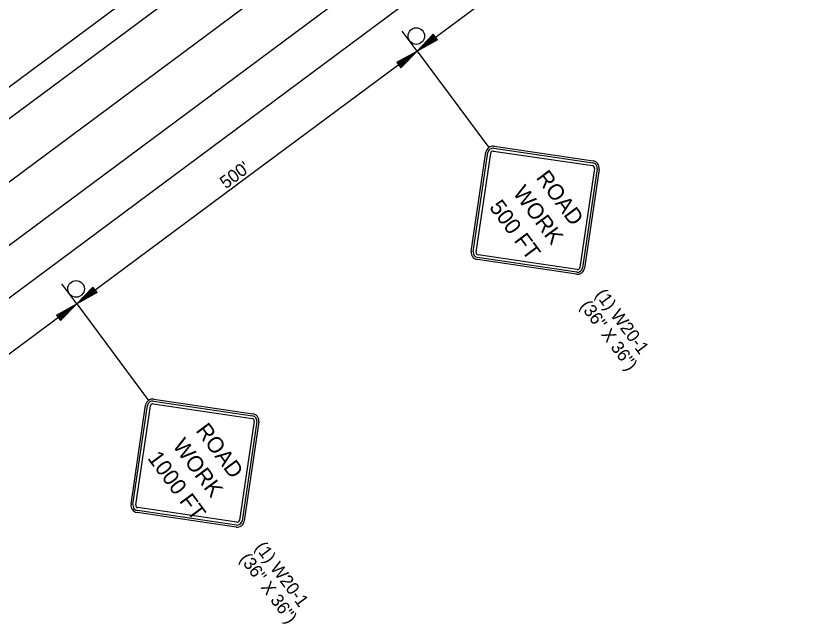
# Model space of a CAD drawing. Extents: x 998982 to 1000630, y 1875366 to 1876934.
# Drawn here: x 999363.5 to 999743.7, y 1875480.6 to 1875767.2 of the extents above; entities that cross this region are included whole.
import ezdxf

# ---------------------------------------------------------------- set-up
doc = ezdxf.new("R2010")
doc.units = 0
for name, color, linetype in [('P_TC_Signs_Temporary', 7, 'Continuous'), ('R_Border Prem', 7, 'Continuous'), ('R_Draft', 7, 'Continuous'), ('STAMP', 7, 'Continuous')]:
    doc.layers.add(name, color=color, linetype=linetype)

msp = doc.modelspace()

# ---------------------------------------------------------------- linework, layer by layer
at = {"layer": 'P_TC_Signs_Temporary'}
for p, q in [((999588.87, 1875704.91), (999635.61, 1875698)), ((999589, 1875705.83), (999635.75, 1875698.93)), ((999578.27, 1875656.25), (999585.17, 1875702.99)), ((999579.19, 1875656.11), (999586.1, 1875702.85)), ((999580.49, 1875655.92), (999587.4, 1875702.66)), ((999588.68, 1875703.61), (999635.42, 1875696.7)), ((999636.37, 1875695.42), (999629.46, 1875648.68)), ((999637.66, 1875695.23), (999630.76, 1875648.49)), ((999638.59, 1875695.1), (999631.69, 1875648.35)), ((999627.85, 1875645.51), (999581.11, 1875652.41)), ((999627.99, 1875646.43), (999581.25, 1875653.34)), ((999628.18, 1875647.73), (999581.44, 1875654.64)), ((999428.43, 1875586.6), (999475.17, 1875579.7)), ((999417.69, 1875537.01), (999424.6, 1875583.76)), ((999418.62, 1875536.88), (999425.53, 1875583.62)), ((999419.92, 1875536.68), (999426.82, 1875583.43)), ((999428.1, 1875584.38), (999474.84, 1875577.47)), ((999428.29, 1875585.67), (999475.04, 1875578.77)), ((999475.79, 1875576.19), (999468.89, 1875529.45)), ((999477.09, 1875576), (999470.19, 1875529.26)), ((999478.02, 1875575.86), (999471.11, 1875529.12)), ((999467.28, 1875526.28), (999420.54, 1875533.18)), ((999467.42, 1875527.2), (999420.68, 1875534.11)), ((999467.61, 1875528.5), (999420.87, 1875535.41))]:
    msp.add_line(p, q, dxfattribs=at)
for centre, radius, start, end in [((999588.51, 1875702.49), 3.38, 81.5953, 171.5953), ((999588.51, 1875702.49), 2.44, 81.5953, 171.5953), ((999588.51, 1875702.49), 1.12, 81.5953, 171.5953), ((999635.25, 1875695.59), 1.13, 351.5953, 81.5953), ((999635.25, 1875695.59), 2.44, 351.5953, 81.5953), ((999635.25, 1875695.59), 3.37, 351.5953, 81.5953), ((999581.6, 1875655.75), 3.37, 171.5953, 261.5953), ((999581.6, 1875655.75), 2.44, 171.5953, 261.5953), ((999581.6, 1875655.75), 1.13, 171.5953, 261.5953), ((999628.35, 1875648.85), 3.38, 261.5953, 351.5953), ((999628.35, 1875648.85), 2.44, 261.5953, 351.5953), ((999628.35, 1875648.85), 1.12, 261.5953, 351.5953), ((999427.94, 1875583.26), 3.38, 81.5953, 171.5953), ((999427.94, 1875583.26), 2.44, 81.5953, 171.5953), ((999427.94, 1875583.26), 1.12, 81.5953, 171.5953), ((999474.68, 1875576.36), 2.44, 351.5953, 81.5953), ((999474.68, 1875576.36), 3.37, 351.5953, 81.5953), ((999474.68, 1875576.36), 1.13, 351.5953, 81.5953), ((999421.03, 1875536.52), 3.37, 171.5953, 261.5953), ((999421.03, 1875536.52), 2.44, 171.5953, 261.5953), ((999421.03, 1875536.52), 1.13, 171.5953, 261.5953), ((999467.77, 1875529.61), 1.12, 261.5953, 351.5953), ((999467.77, 1875529.61), 3.38, 261.5953, 351.5953), ((999467.77, 1875529.61), 2.44, 261.5953, 351.5953)]:
    msp.add_arc(centre, radius, start, end, dxfattribs=at)
at = {"layer": 'R_Draft'}
for p, q in [((999192.61, 1875564.71), (999743.69, 1875973.9)), ((999171.2, 1875593.53), (999643.2, 1875944.01)), ((999178.34, 1875583.93), (999650.33, 1875934.4)), ((999206.88, 1875545.49), (999678.87, 1875895.96)), ((999218.77, 1875529.47), (999690.77, 1875879.94)), ((999713.25, 1875869.99), (999552.67, 1875750.76)), ((999560.31, 1875758.68), (999552.67, 1875750.76)), ((999560.48, 1875758.46), (999554.11, 1875751.87)), ((999560.65, 1875758.24), (999555.6, 1875753)), ((999560.81, 1875758.03), (999557.03, 1875754.11)), ((999560.98, 1875757.81), (999558.5, 1875755.23)), ((999561.15, 1875757.59), (999559.94, 1875756.34)), ((999562.29, 1875756.09), (999560.31, 1875758.68)), ((999562.29, 1875756.09), (999552.67, 1875750.76)), ((999562.13, 1875756.3), (999554.11, 1875751.87)), ((999561.96, 1875756.53), (999555.6, 1875753)), ((999561.79, 1875756.74), (999557.03, 1875754.11)), ((999561.62, 1875756.97), (999558.5, 1875755.23)), ((999561.46, 1875757.18), (999559.94, 1875756.34)), ((999552.67, 1875750.76), (999472.39, 1875691.14)), ((999543.05, 1875745.43), (999552.67, 1875750.76)), ((999545.04, 1875742.84), (999552.67, 1875750.76)), ((999552.67, 1875750.76), (999586.5, 1875705.2)), ((999543.22, 1875745.21), (999551.23, 1875749.65)), ((999543.38, 1875744.99), (999549.75, 1875748.51)), ((999543.55, 1875744.78), (999548.31, 1875747.41)), ((999543.72, 1875744.55), (999546.85, 1875746.29)), ((999544.37, 1875743.71), (999546.85, 1875746.29)), ((999544.54, 1875743.49), (999548.31, 1875747.41)), ((999544.7, 1875743.28), (999549.75, 1875748.51)), ((999544.87, 1875743.05), (999551.23, 1875749.65)), ((999543.05, 1875745.43), (999545.04, 1875742.84)), ((999543.89, 1875744.34), (999545.41, 1875745.18)), ((999544.2, 1875743.93), (999545.41, 1875745.18)), ((999472.39, 1875691.14), (999392.1, 1875631.53)), ((999399.74, 1875639.45), (999392.1, 1875631.53)), ((999401.72, 1875636.86), (999392.1, 1875631.53)), ((999399.9, 1875639.23), (999393.54, 1875632.64)), ((999401.56, 1875637.07), (999393.54, 1875632.64)), ((999400.07, 1875639.01), (999395.02, 1875633.77)), ((999401.39, 1875637.29), (999395.02, 1875633.77)), ((999400.24, 1875638.8), (999396.46, 1875634.88)), ((999401.22, 1875637.51), (999396.46, 1875634.88)), ((999400.41, 1875638.58), (999397.93, 1875636)), ((999401.05, 1875637.73), (999397.93, 1875636)), ((999400.57, 1875638.36), (999399.37, 1875637.11)), ((999400.89, 1875637.95), (999399.37, 1875637.11)), ((999401.72, 1875636.86), (999399.74, 1875639.45)), ((999392.1, 1875631.53), (999231.53, 1875512.3)), ((999382.48, 1875626.2), (999392.1, 1875631.53)), ((999382.64, 1875625.98), (999390.66, 1875630.42)), ((999382.81, 1875625.76), (999389.17, 1875629.28)), ((999382.98, 1875625.55), (999387.74, 1875628.18)), ((999383.96, 1875624.26), (999387.74, 1875628.18)), ((999384.13, 1875624.04), (999389.17, 1875629.28)), ((999384.3, 1875623.82), (999390.66, 1875630.42)), ((999384.46, 1875623.6), (999392.1, 1875631.53)), ((999392.1, 1875631.53), (999425.93, 1875585.97)), ((999382.48, 1875626.2), (999384.46, 1875623.6)), ((999383.15, 1875625.32), (999386.27, 1875627.05)), ((999383.31, 1875625.11), (999384.84, 1875625.95)), ((999383.62, 1875624.7), (999384.84, 1875625.95)), ((999383.79, 1875624.48), (999386.27, 1875627.05))]:
    msp.add_line(p, q, dxfattribs=at)
at = {"layer": 'STAMP'}
for p, q in [((999552.67, 1875750.76), (999545.67, 1875760.2)), ((999392.1, 1875631.53), (999385.1, 1875640.97))]:
    msp.add_line(p, q, dxfattribs=at)
for centre in [(999552.32, 1875757.81), (999391.75, 1875638.58)]:
    msp.add_circle(centre, 3.92, dxfattribs=at)

# ---------------------------------------------------------------- texts
at = {"layer": 'P_TC_Signs_Temporary'}
for s, p in [(' ROAD ', (999606.87, 1875693.22)), ('WORK', (999597.63, 1875683.83)), ('500 FT ', (999586.44, 1875677.04)), (' ROAD ', (999446.3, 1875573.99)), ('WORK', (999437.05, 1875564.6)), ('1000 FT', (999425.23, 1875558.68))]:
    msp.add_text(s, height=7.5, rotation=306.5953, dxfattribs=at).set_placement(p)
at = {"layer": 'R_Border Prem'}
for s, rotation, p in [("500'", 36.5953, (999462.41, 1875685.51)), ('(1) W20-1', 306.5953, (999636.49, 1875635.86)), ('(36" X 36")', 306.5953, (999629.27, 1875630.5)), ('(1) W20-1', 306.5953, (999475.92, 1875516.63)), ('(36" X 36")', 306.5953, (999468.69, 1875511.26))]:
    msp.add_text(s, height=6, rotation=rotation, dxfattribs=at).set_placement(p)

doc.saveas('drawing.dxf')
